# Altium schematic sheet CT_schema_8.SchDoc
size 297 x 239 mm
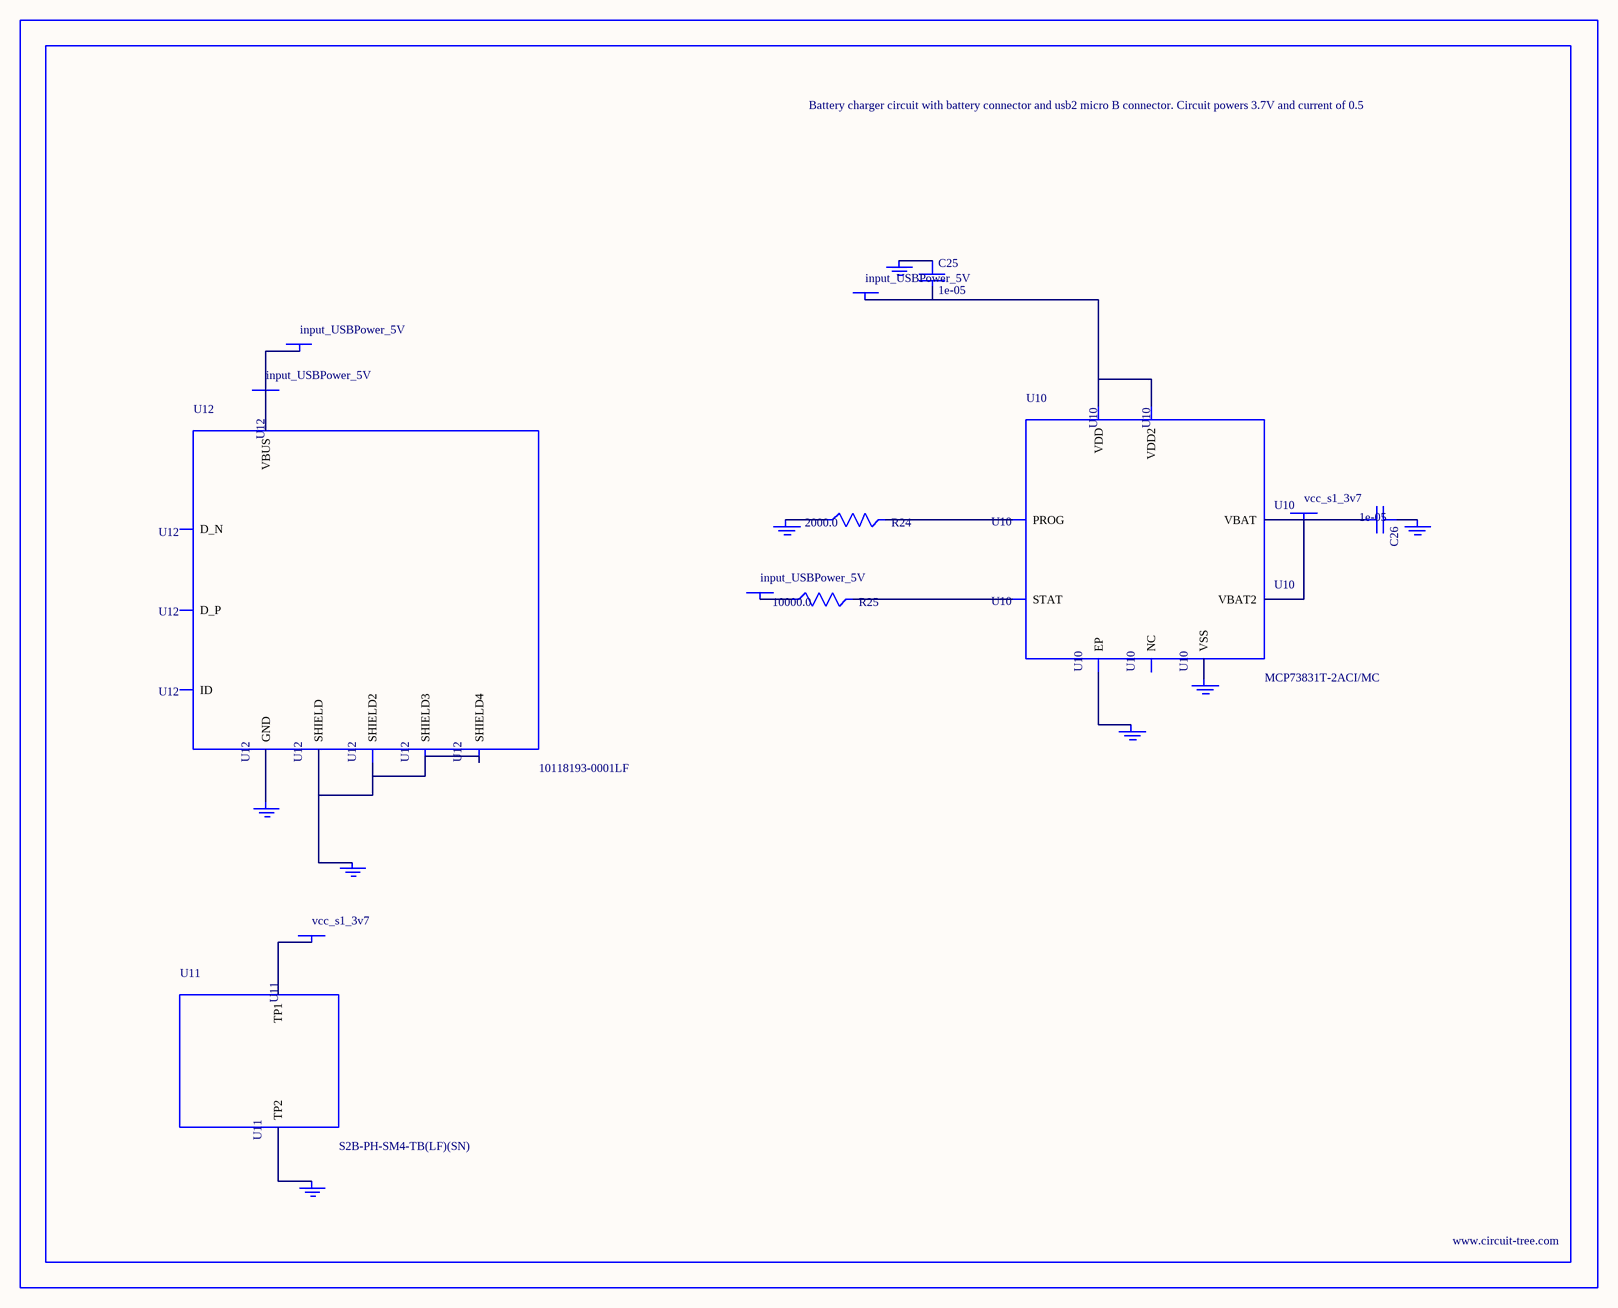
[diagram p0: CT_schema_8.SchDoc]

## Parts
BORDER7  (no value)
C25  1e-05  [C1206]
C26  1e-05  [C1206]
GND_INSTANCE_7_0  (no value)
GND_INSTANCE_7_1  (no value)
GND_INSTANCE_7_2  (no value)
GND_INSTANCE_7_3  (no value)
GND_INSTANCE_7_4  (no value)
GND_INSTANCE_7_5  (no value)
GND_INSTANCE_7_6  (no value)
GND_INSTANCE_7_7  (no value)
POWER_INSTANCE_7_0  input_USBPower_5V
POWER_INSTANCE_7_1  input_USBPower_5V
POWER_INSTANCE_7_2  vcc_s1_3v7
POWER_INSTANCE_7_3  vcc_s1_3v7
POWER_INSTANCE_7_4  input_USBPower_5V
POWER_INSTANCE_7_5  input_USBPower_5V
R24  2000.0  [R0603]
R25  10000.0  [R0603]
U10  MCP73831T-2ACI/MC  [DFN8_2X3MC]
U11  S2B-PH-SM4-TB(LF)(SN)  [JST-2-SMD]
U12  10118193-0001LF  [FCI_10118193-0001LF]

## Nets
NetC25_1: C25.1 GND_INSTANCE_7_0.0(GND)
NetC25_2: C25.2 POWER_INSTANCE_7_0.0(PWR) U10.1(VDD) U10.2(VDD2)
NetC26_1: C26.1 GND_INSTANCE_7_1.0(GND)
NetC26_2: C26.2 POWER_INSTANCE_7_2.0(PWR) U10.3(VBAT) U10.4(VBAT2)
NetGND_INSTANCE_7_2_0: GND_INSTANCE_7_2.0(GND) R24.1
NetGND_INSTANCE_7_3_0: GND_INSTANCE_7_3.0(GND) U10.9(EP)
NetGND_INSTANCE_7_4_0: GND_INSTANCE_7_4.0(GND) U10.6(VSS)
NetGND_INSTANCE_7_5_0: GND_INSTANCE_7_5.0(GND) U11.2(TP2)
NetGND_INSTANCE_7_6_0: GND_INSTANCE_7_6.0(GND) U12.6(SHIELD) U12.7(SHIELD2) U12.8(SHIELD3) U12.9(SHIELD4)
NetGND_INSTANCE_7_7_0: GND_INSTANCE_7_7.0(GND) U12.5(GND)
NetPOWER_INSTANCE_7_1_0: POWER_INSTANCE_7_1.0(PWR) R25.1
NetPOWER_INSTANCE_7_3_0: POWER_INSTANCE_7_3.0(PWR) U11.1(TP1)
NetPOWER_INSTANCE_7_4_0: POWER_INSTANCE_7_4.0(PWR) POWER_INSTANCE_7_5.0(PWR) U12.1(VBUS)
NetR24_2: R24.2 U10.8(PROG)
NetR25_2: R25.2 U10.5(STAT)

Not connected (* = marked no-connect by the designer): U10 7(NC); U12 2(D_N) 3(D_P) 4(ID)

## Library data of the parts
BORDER7 = BORDER_PAGE7
C25 C26 = C1206C106K3RACTU
GND_INSTANCE_7_0-GND_INSTANCE_7_7 = GND
POWER_INSTANCE_7_0-POWER_INSTANCE_7_5 = PWR
R24 = RC0603JR-072KL
R25 = RC0603JR-0710KL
